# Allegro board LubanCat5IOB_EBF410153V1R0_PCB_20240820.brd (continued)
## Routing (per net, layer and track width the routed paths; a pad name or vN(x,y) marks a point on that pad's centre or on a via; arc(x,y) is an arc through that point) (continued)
SDMMC_D3: length 115.6
  TOP w0.173: J4.75 v2(82.84,64.36) ; R278.1 v1(151.54,23.76)
  ART04 w0.16: v2(82.84,64.36) 82.36,64.84 80.38,64.84 80.04,64.5 80.04,62.47 80.46,62.04 80.46,52.35 83.71,49.1 95.27,49.1 96.19,48.17 105.48,48.17 106.4,49.1 114.41,49.1 115.38,50.07 127.87,50.07 128.34,49.6 141.31,49.6 147.37,43.53 147.37,37.72 147.58,37.51 150.43,37.51 150.75,37.19 150.75,36.9 150.56,36.71 149.06,36.71 148.87,36.52 148.87,36.26 149.06,36.07 150.56,36.07 150.75,35.88 150.75,24.55 v1(151.54,23.76)
SDMMC_DET: length 118.2
  TOP w0.152: v2(83.64,63.52) 84.04,63.92 J4.81 ; R283.1 v1(151.51,16.02) R284.2
  ART04 w0.152: v2(83.64,63.52) 83.87,63.29 83.87,55.8
  ART04 w0.16: 83.87,55.8 87.26,52.42 112.83,52.42 114.12,53.71 142.49,53.71 154.66,41.54 154.66,31.38 155.78,30.27 155.78,20.97 155.46,20.65 152.49,20.65 152.1,20.26 152.1,16.6 v1(151.51,16.02)
SIM_CLK0: length 44.1
  TOP w0.152: J23.12 140.1,59.74 142,57.84 142,40.67 142.68,39.99 147.65,39.99 148.23,39.41 148.23,27.73 v1(147.57,27.07)
  BOTTOM w0.173: R259.1 v1(147.57,27.07)
SIM_DATA0: length 45.1
  TOP w0.152: v1(147.57,25.92) 148.74,27.09 148.74,40.03 147.98,40.79 143.45,40.79 142.8,41.44 142.8,58.05 140.9,59.95 J23.10
  BOTTOM w0.173: R260.1 v1(147.57,25.92)
SIM_RST0: length 43
  TOP w0.152: J23.14 139.3,59.55 141.2,57.65 141.2,40.15 142.15,39.19 147.32,39.19 147.65,38.86 147.65,28.29 v1(147.57,28.21)
  BOTTOM w0.173: R258.1 v1(147.57,28.21)
SIM_VDD: length 65.9
  TOP w0.254: J23.8 141.7,60.17 143.6,58.27 143.6,42.1 144.11,41.59 150.24,41.59 150.75,41.08 150.75,27.7 151.26,27.19 ; v1(157.15,27.19) v1(160.15,27.19) ; v1(147.57,24.78) 149.3,26.51 150.57,26.51 151.26,27.19 ; 151.26,27.19 v1(154.17,27.19)
  BOTTOM w0.254: R253.1 v1(147.57,24.78) ; v1(160.15,27.19) 160.15,23.28 159.64,22.77 J21.1 ; v1(154.17,27.19) U30.6 155.41,27.87 156.08,27.19 v1(157.15,27.19)
SPK_CTRL: length 88.1
  TOP w0.152: J4.58 79.24,67.32 v2(78.84,66.92) ; R345.1 26.04,69.1 v1(26.16,69.23) ; v1(36.2,67.97) R351.1 36.96,67.48 37.26,67.17 39.95,67.17 40.26,67.48 40.26,69.08 40.83,69.65 v1(52.41,69.65)
  ART03 w0.152: v1(36.2,67.97) 35.37,68.8 33.38,68.8 32.94,69.23 v1(26.16,69.23)
  ART04 w0.152: v1(52.41,69.65) 53.37,68.69 53.37,54.35 54.46,53.25 73.53,53.25 74.47,54.19 74.47,66.26 75.03,66.82 75.03,68.01 75.34,68.32 77.44,68.32 v2(78.84,66.92)
SPK_LN: length 5.8
  TOP w0.381: L19.2 28.19,82.32 C301.1 27.16,83.35 J42.1
SPK_LP: length 5.7
  TOP w0.381: L27.2 24.38,82.45 C300.1 25.16,83.22 J42.2
SPK_RN: length 5.8
  TOP w0.381: J43.1 38.45,83.37 C311.1 39.5,82.32 L28.2
SPK_RP: length 5.7
  TOP w0.381: J43.2 36.45,83.08 C310.1 35.69,82.32 L29.2
SYS_LED: length 200.4
  TOP w0.152: v1(80.64,41.46) 80.64,29.43 81.1,28.97 81.1,23.81 80.84,23.55 J2.65 ; v1(157.71,41.87) 157.71,34.9 158.01,34.59 169.91,34.59 170.26,34.94 170.26,83.91 169.91,84.25 167.66,84.25 167.31,84.6 167.31,94.89 166.55,95.66 151.1,95.66 150.76,96 R334.1
  ART03 w0.152: v1(114.84,43.18) 113.54,41.87 110.97,41.87 108.61,39.51 82.59,39.51 v1(80.64,41.46)
  BOTTOM w0.152: v1(114.84,43.18) 115.44,42.58 130.38,42.58 131,41.96 157.62,41.96 v1(157.71,41.87)
TYPEC0_SBU1: length 72.4
  TOP w0.132: J3.84 58.87,68.99 58.95,69.07 58.95,69.29 v2(58.67,69.57)
  ART03 w0.114: v2(58.67,69.57) 58.93,69.32 58.93,68.31 59.88,67.35 63.1,67.35 64.07,68.32 64.07,82.3 63.58,82.79 60.3,82.79 59.72,83.38 46.18,83.38 45.06,82.26 42.93,82.26 42.29,82.9 40.03,82.9 38.4,84.52 38.4,85.51 37.59,86.32 37.59,88.14 v1(37.85,88.41)
  BOTTOM w0.132: v1(37.85,88.41) 37.59,88.67 37.59,89.14 37.19,89.55 31.04,89.55 29.93,88.44 23.42,88.44 22.85,89.01 22.85,90.04 C84.2
TYPEC0_SBU1_DC: length 97.9
  TOP w0.152: J4.93 86.44,63.92 v2(86.04,63.52)
  ART04 w0.152: v2(86.04,63.52) 86.47,63.95 88.06,63.95 88.24,64.12 88.24,66.99 87.91,67.32 86.23,67.32 85.9,67.66 83.59,67.66 83.29,67.96 83.29,68.93 82.98,69.23 81.05,69.23 80.75,69.53 80.75,71.97 80.44,72.28 52.5,72.28 51.36,73.42 49.83,73.42 49.53,73.73 49.53,80.28 50.16,80.91 50.16,83.02 50.47,83.33 51.64,83.33 51.94,83.63 51.94,86.3 51.1,87.14 51.1,89.04 50.52,89.63 28.19,89.63 27.03,90.79 24.81,90.79 v1(24.25,90.24)
  BOTTOM w0.173: R92.2 v1(24.25,90.24)
TYPEC0_SBU2: length 71.6
  TOP w0.132: J3.86 59.27,69.09 59.19,69.17 59.19,69.34 v2(59.42,69.57)
  ART03 w0.114: v2(59.42,69.57) 59.17,69.32 59.17,68.41 59.98,67.59 63,67.59 63.83,68.42 63.83,82.2 63.48,82.55 60.2,82.55 59.62,83.14 46.28,83.14 45.16,82.02 42.83,82.02 42.19,82.65 39.93,82.65 38.16,84.42 38.16,85.41 37.35,86.22 37.35,88.14 v1(37.09,88.41)
  BOTTOM w0.132: C85.2 22.61,90.04 22.61,88.91 23.32,88.2 30.03,88.2 31.13,89.31 37.09,89.31 37.35,89.04 37.35,88.67 v1(37.09,88.41)
TYPEC0_SBU2_DC: length 93.3
  TOP w0.152: J4.95 v2(86.84,64.36)
  ART04 w0.152: v1(20.46,90.67) 23.04,90.67 24.58,89.13 48.26,89.13 48.64,88.75 48.64,87.14 49.91,85.87 49.91,84.09 49.15,83.33 49.15,73.22 49.45,72.91 51,72.91 51.31,72.61 51.31,71.95 51.61,71.64 56.67,71.64 57.18,71.13 64.08,71.13 64.69,71.74 77.37,71.74 78.05,71.06 79.91,71.06 80.21,70.75 80.21,69 80.52,68.7 82.14,68.7 82.45,68.39 82.45,66.56 82.68,66.33 83.01,66.33 83.39,65.95 86.48,65.95 86.84,65.6 v2(86.84,64.36)
  BOTTOM w0.152: v1(20.46,90.67) 20.46,91.69 R94.2
TYPEC0_SSRX1N: length 52.3
  TOP w0.132: R86.2 30.4,90.86 arc(30.36,90.8) 30.35,90.73 30.35,90.61 arc(30.41,90.28) 30.6,89.99 arc(30.81,89.85) 31.06,89.8 33.01,89.8 arc(33.42,89.72) 33.78,89.49 33.91,89.36 arc(34.14,89) 34.22,88.59 34.22,86.16 arc(34.25,86.05) 34.31,85.95 v1(34.5,85.77) ; J3.80 58.07,67.98 57.99,67.9 57.99,67.78 arc(58.01,67.69) 58.06,67.61 v2(58.27,67.4)
  ART03 w0.114: v1(34.5,85.77) 34.35,85.62 arc(34.25,85.47) 34.21,85.29 34.21,84.73 arc(34.24,84.58) 34.33,84.46 34.47,84.32 arc(34.59,84.23) 34.74,84.2 35.62,84.2 arc(35.9,84.15) 36.14,83.99 36.29,83.85 arc(36.44,83.61) 36.5,83.33 36.5,82.35 arc(36.64,82) 36.99,81.85 38.22,81.85 arc(38.44,81.81) 38.62,81.69 39.05,81.26 arc(39.43,81) 39.88,80.91 41.67,80.91 arc(41.89,80.87) 42.08,80.75 42.17,80.65 arc(42.3,80.56) 42.46,80.53 45.09,80.53 arc(45.5,80.61) 45.84,80.84 46.55,81.55 arc(47.03,81.87) 47.58,81.98 57.05,81.98 arc(57.43,81.9) 57.76,81.69 arc(57.98,81.36) 58.05,80.98 58.05,75.54 arc(58.12,75.19) 58.32,74.89 arc(58.58,74.5) 58.67,74.04 58.67,70.73 arc(58.6,70.38) 58.4,70.07 arc(58.22,69.8) 58.15,69.48 58.15,67.69 arc(58.18,67.53) v2(58.27,67.4)
TYPEC0_SSRX1P: length 53.2
  TOP w0.132: v2(57.52,67.4) 57.7,67.58 arc(57.74,67.64) 57.75,67.7 57.75,67.8 57.67,67.88 J3.78 ; v1(33.71,85.77) 33.9,85.95 arc(33.96,86.05) 33.99,86.16 33.99,86.42 arc(33.93,86.55) 33.79,86.61 arc(33.66,86.66) 33.6,86.8 33.6,86.95 arc(33.66,87.08) 33.79,87.14 arc(33.93,87.19) 33.99,87.33 33.99,88.59 arc(33.92,88.91) 33.74,89.19 33.61,89.32 arc(33.33,89.5) 33.01,89.57 31.06,89.57 arc(30.72,89.63) 30.43,89.82 arc(30.19,90.19) 30.11,90.61 30.11,90.73 arc(30.09,90.8) 30.05,90.86 R85.2
  ART03 w0.114: v1(33.71,85.77) 33.85,85.63 arc(33.94,85.49) 33.97,85.33 33.97,84.73 arc(34.02,84.49) 34.16,84.29 34.3,84.15 arc(34.5,84.01) 34.74,83.96 35.62,83.96 arc(35.81,83.93) 35.97,83.82 36.12,83.67 arc(36.22,83.52) 36.26,83.33 36.26,82.35 arc(36.47,81.83) 36.99,81.61 38.22,81.61 arc(38.35,81.59) 38.45,81.52 38.88,81.09 arc(39.34,80.78) 39.88,80.67 41.67,80.67 arc(41.8,80.65) 41.91,80.58 42,80.48 arc(42.21,80.34) 42.46,80.29 45.09,80.29 arc(45.59,80.39) 46.01,80.67 46.72,81.38 arc(47.12,81.65) 47.58,81.74 57.05,81.74 arc(57.34,81.68) 57.59,81.52 arc(57.75,81.27) 57.81,80.98 57.81,75.54 arc(57.9,75.1) 58.15,74.72 arc(58.36,74.41) 58.43,74.04 58.43,70.73 arc(58.38,70.47) 58.23,70.24 arc(57.99,69.89) 57.91,69.48 57.91,68.96 arc(57.86,68.84) 57.75,68.79 arc(57.63,68.74) 57.58,68.63 57.58,68.5 arc(57.63,68.38) 57.75,68.33 arc(57.86,68.29) 57.91,68.17 57.91,67.93 arc(57.89,67.8) 57.81,67.69 v2(57.52,67.4)
TYPEC0_SSRX2N: length 51.7
  TOP w0.132: J3.70 56.07,67.98 55.99,67.9 55.99,67.78 arc(56.01,67.69) 56.06,67.61 v2(56.27,67.4) ; v1(30.1,85.74) 29.86,85.98 arc(29.82,86.04) 29.8,86.12 29.8,87.22 arc(29.71,87.7) 29.44,88.1 29.36,88.18 arc(28.96,88.45) 28.48,88.54 24.29,88.54 arc(24.08,88.59) 23.9,88.7 arc(23.78,88.88) 23.74,89.09 23.74,90.73 arc(23.76,90.8) 23.8,90.86 R91.2
  ART03 w0.114: v1(30.1,85.74) 29.96,85.6 arc(29.86,85.45) 29.83,85.29 29.83,85.27 arc(29.86,85.13) 29.93,85.02 33.55,81.4 34.48,80.47 arc(34.78,80.27) 35.13,80.2 arc(35.86,80.06) 36.47,79.65 36.74,79.38 arc(37.11,79.13) 37.55,79.05 47.89,79.05 arc(48.29,78.97) 48.63,78.74 arc(48.92,78.54) 49.27,78.48 53.8,78.48 arc(54.62,78.13) 54.97,77.31 54.97,74.51 arc(55.04,74.14) 55.25,73.82 55.79,73.28 arc(56.13,72.77) 56.25,72.17 56.25,68.96 arc(56.21,68.77) 56.1,68.6 56.1,68.6 arc(56.04,68.51) 56.02,68.41 56.02,67.82 arc(56.05,67.67) 56.14,67.54 v2(56.27,67.4)
TYPEC0_SSRX2P: length 52
  TOP w0.132: J3.68 55.67,67.88 55.75,67.8 55.75,67.7 arc(55.74,67.64) 55.7,67.58 v2(55.52,67.4) ; R89.2 23.45,90.86 arc(23.49,90.8) 23.5,90.73 23.5,90.47 arc(23.46,90.36) 23.35,90.31 arc(23.24,90.27) 23.19,90.16 23.19,89.94 arc(23.24,89.83) 23.35,89.78 arc(23.46,89.74) 23.5,89.63 23.5,89.09 arc(23.56,88.79) 23.73,88.54 arc(23.99,88.37) 24.29,88.31 28.48,88.31 arc(28.87,88.23) 29.2,88.01 29.27,87.94 arc(29.49,87.61) 29.57,87.22 29.57,86.13 arc(29.54,86) 29.47,85.89 v1(29.32,85.74)
  ART03 w0.114: v1(29.32,85.74) 29.46,85.6 arc(29.56,85.45) 29.59,85.29 29.59,85.27 arc(29.63,85.04) 29.76,84.84 33.38,81.23 34.31,80.3 arc(34.68,80.05) 35.13,79.96 arc(35.76,79.84) 36.3,79.48 36.57,79.21 arc(37.02,78.91) 37.55,78.81 47.89,78.81 arc(48.2,78.74) 48.46,78.57 arc(48.83,78.32) 49.27,78.23 53.8,78.23 arc(54.45,77.96) 54.72,77.31 54.72,74.51 arc(54.82,74.05) 55.08,73.65 55.62,73.11 arc(55.91,72.68) 56.01,72.17 56.01,68.96 arc(55.99,68.86) 55.93,68.77 arc(55.82,68.6) 55.78,68.41 55.78,67.82 arc(55.75,67.67) 55.66,67.54 v2(55.52,67.4)
TYPEC0_SSTX1N: length 50.7
  TOP w0.132: J3.76 57.27,69.09 57.19,69.17 57.19,69.27 arc(57.21,69.34) 57.24,69.39 v2(57.42,69.57) ; C80.2 28.02,90.86 arc(28.06,90.8) 28.07,90.73 28.07,90.16 arc(28.13,89.89) 28.29,89.65 28.36,89.58 arc(28.71,89.34) 29.13,89.26 arc(29.7,89.15) 30.18,88.82 30.94,88.07 arc(31.31,87.51) 31.45,86.85 31.45,86.13 arc(31.42,86.02) 31.36,85.93 v1(31.17,85.74)
  ART03 w0.114: v2(57.42,69.57) 57.29,69.71 arc(57.2,69.84) 57.17,69.99 57.17,78.97 arc(57.12,79.22) 56.98,79.44 56.9,79.52 arc(56.68,79.66) 56.43,79.71 55.84,79.71 arc(55.48,79.78) 55.17,79.98 55.11,80.05 arc(54.68,80.33) 54.18,80.43 48.87,80.43 arc(48.47,80.35) 48.13,80.13 arc(47.74,79.86) 47.27,79.77 40.17,79.77 arc(39.57,79.89) 39.07,80.23 38.76,80.54 arc(38.39,80.78) 37.97,80.86 36.6,80.86 arc(36.32,80.92) 36.08,81.08 35.87,81.29 arc(35.72,81.52) 35.66,81.8 35.66,82.33 arc(35.38,83) 34.71,83.28 arc(34.36,83.35) 34.05,83.55 33.63,83.97 arc(33.37,84.37) 33.27,84.83 33.27,86.39 arc(33.21,86.69) 33.04,86.95 arc(32.72,87.17) 32.33,87.24 arc(32,87.18) 31.72,86.99 31.63,86.9 arc(31.49,86.7) 31.44,86.45 31.44,86.19 arc(31.41,86.03) 31.32,85.88 v1(31.17,85.74)
TYPEC0_SSTX1P: length 50.8
  TOP w0.132: C79.2 28.37,90.86 arc(28.33,90.8) 28.31,90.73 28.31,90.16 arc(28.35,89.98) 28.45,89.82 28.53,89.75 arc(28.8,89.56) 29.13,89.5 arc(29.79,89.37) 30.35,88.99 31.11,88.24 arc(31.53,87.6) 31.68,86.85 31.68,86.13 arc(31.71,86.02) 31.77,85.93 v1(31.96,85.74) ; v2(56.67,69.57) 56.89,69.36 arc(56.94,69.29) 56.95,69.2 56.95,69.07 56.87,68.99 J3.74
  ART03 w0.114: v2(56.67,69.57) 56.86,69.76 arc(56.91,69.83) 56.93,69.92 56.93,70.16 arc(56.89,70.24) 56.81,70.28 arc(56.73,70.31) 56.69,70.39 56.69,70.62 arc(56.73,70.7) 56.81,70.74 arc(56.89,70.77) 56.93,70.85 56.93,71.08 arc(56.89,71.16) 56.81,71.19 arc(56.73,71.23) 56.69,71.31 56.69,71.53 arc(56.73,71.62) 56.81,71.65 arc(56.89,71.68) 56.93,71.77 56.93,71.99 arc(56.89,72.07) 56.81,72.11 arc(56.73,72.14) 56.69,72.22 56.69,72.45 arc(56.73,72.53) 56.81,72.56 arc(56.89,72.6) 56.93,72.68 56.93,78.97 arc(56.9,79.13) 56.81,79.27 56.73,79.35 arc(56.59,79.43) 56.43,79.47 55.84,79.47 arc(55.38,79.56) 55,79.81 54.94,79.88 arc(54.59,80.11) 54.18,80.19 48.87,80.19 arc(48.56,80.13) 48.31,79.96 48.3,79.96 arc(47.83,79.64) 47.27,79.53 40.17,79.53 arc(39.48,79.67) 38.9,80.06 38.59,80.36 arc(38.3,80.56) 37.97,80.62 36.6,80.62 arc(36.23,80.7) 35.91,80.9 35.7,81.12 arc(35.49,81.43) 35.42,81.8 35.42,82.33 arc(35.21,82.83) 34.71,83.03 arc(34.26,83.12) 33.88,83.38 33.46,83.8 arc(33.14,84.27) 33.03,84.83 33.03,86.39 arc(32.99,86.6) 32.87,86.77 32.87,86.78 arc(32.62,86.94) 32.33,87 arc(32.09,86.95) 31.89,86.82 31.8,86.73 arc(31.72,86.6) 31.69,86.45 31.69,86.19 arc(31.72,86.03) 31.81,85.88 v1(31.96,85.74)
TYPEC0_SSTX2N: length 52.6
  TOP w0.132: C83.2 21.42,90.86 arc(21.46,90.8) 21.47,90.73 21.47,90.33 arc(21.51,90.13) 21.62,89.97 22.24,89.35 arc(22.45,89.04) 22.52,88.68 22.52,87.84 arc(22.5,87.73) 22.43,87.63 v1(22.25,87.44) ; v2(55.42,69.57) 55.24,69.39 arc(55.21,69.34) 55.19,69.27 55.19,69.17 55.27,69.09 J3.66
  ART03 w0.114: v1(22.25,87.44) 22.39,87.59 arc(22.49,87.73) 22.52,87.9 22.52,88.13 arc(22.7,88.56) 23.13,88.74 23.78,88.74 arc(24.15,88.58) 24.31,88.21 24.31,86.05 arc(24.66,85.19) 25.52,84.84 28.01,84.84 arc(28.65,84.71) 29.19,84.35 32.78,80.76 arc(33.13,80.24) 33.25,79.63 arc(33.29,79.4) 33.42,79.21 arc(33.62,79.08) 33.84,79.03 34.83,79.03 arc(35.2,78.96) 35.51,78.75 35.6,78.67 arc(36.34,78.17) 37.23,77.99 47.64,77.99 arc(47.86,77.95) 48.05,77.83 48.27,77.6 arc(48.4,77.52) 48.55,77.48 53.32,77.48 arc(53.85,77.26) 54.08,76.73 54.08,74.33 arc(54.18,73.82) 54.47,73.38 54.74,73.11 arc(55.06,72.64) 55.17,72.08 55.17,69.99 arc(55.2,69.84) 55.29,69.71 v2(55.42,69.57)
TYPEC0_SSTX2P: length 53.3
  TOP w0.132: J3.64 54.87,68.99 54.95,69.07 54.95,69.2 arc(54.94,69.29) 54.89,69.36 v2(54.67,69.57) ; v1(23.03,87.44) 22.84,87.63 arc(22.78,87.73) 22.76,87.84 22.76,88.68 arc(22.67,89.13) 22.41,89.51 21.79,90.14 arc(21.73,90.23) 21.71,90.33 21.71,90.73 arc(21.72,90.8) 21.76,90.86 C82.2
  ART03 w0.114: v2(54.67,69.57) 54.81,69.71 arc(54.9,69.84) 54.93,69.99 54.93,70.23 arc(54.89,70.33) 54.79,70.37 arc(54.7,70.41) 54.66,70.5 54.66,70.69 arc(54.7,70.78) 54.79,70.82 arc(54.89,70.86) 54.93,70.96 54.93,71.2 arc(54.88,71.3) 54.78,71.34 arc(54.68,71.39) 54.64,71.49 54.64,71.66 arc(54.68,71.76) 54.78,71.8 arc(54.88,71.84) 54.93,71.95 54.93,72.08 arc(54.83,72.55) 54.57,72.94 54.3,73.21 arc(53.96,73.73) 53.84,74.33 53.84,76.73 arc(53.68,77.09) 53.32,77.24 48.55,77.24 arc(48.31,77.29) 48.1,77.43 47.88,77.65 arc(47.77,77.73) 47.64,77.75 37.23,77.75 arc(36.25,77.95) 35.42,78.5 35.34,78.58 arc(35.11,78.74) 34.83,78.79 33.84,78.79 arc(33.52,78.86) 33.25,79.04 arc(33.07,79.31) 33.01,79.63 arc(32.9,80.15) 32.61,80.59 29.02,84.18 arc(28.56,84.49) 28.01,84.6 25.52,84.6 arc(24.49,85.02) 24.07,86.05 24.07,86.3 arc(24.02,86.4) 23.92,86.45 23.87,86.45 arc(23.77,86.49) 23.72,86.59 23.72,86.76 arc(23.77,86.86) 23.87,86.9 23.92,86.9 arc(24.02,86.95) 24.07,87.05 24.07,87.22 arc(24.02,87.32) 23.92,87.36 arc(23.82,87.4) 23.77,87.51 23.77,87.67 arc(23.82,87.78) 23.92,87.82 arc(24.02,87.86) 24.07,87.97 24.07,88.21 arc(23.98,88.41) 23.78,88.5 23.13,88.5 arc(22.87,88.39) 22.76,88.13 22.76,87.9 arc(22.79,87.73) 22.89,87.59 v1(23.03,87.44)
TYPEC0_USB20_OTG_DM: length 63.7
  TOP w0.132: J3.98 61.67,69.09 61.59,69.17 61.59,69.41 arc(61.63,69.58) 61.72,69.73 v2(61.87,69.88) ; v1(25.52,89.57) 25.7,89.76 arc(25.77,89.86) 25.79,89.97 25.79,91.06 arc(25.75,91.15) 25.66,91.19 R82.2
  ART03 w0.114: v2(61.87,69.88) 61.71,69.72 arc(61.61,69.56) 61.57,69.37 61.57,68.89 arc(61.68,68.61) 61.96,68.49 62.51,68.49 arc(62.8,68.61) 62.92,68.9 62.92,70.34 arc(62.89,70.46) 62.82,70.57 62.59,70.8 arc(62.46,70.99) 62.42,71.21 62.42,74.94 arc(62.46,75.15) 62.59,75.34 62.88,75.63 arc(62.95,75.74) 62.98,75.87 62.98,80.78 arc(62.81,81.19) 62.4,81.36 59.39,81.36 arc(58.96,81.44) 58.61,81.68 58.19,82.1 arc(57.83,82.34) 57.4,82.43 47.3,82.43 arc(46.67,82.3) 46.14,81.95 45.76,81.56 arc(45.28,81.24) 44.72,81.13 42.71,81.13 arc(42.4,81.19) 42.13,81.37 arc(41.8,81.59) 41.43,81.66 40.31,81.66 arc(39.56,81.81) 38.93,82.24 35.6,85.56 arc(35.34,85.96) 35.24,86.43 35.24,86.98 arc(35.18,87.29) 35,87.56 arc(34.62,87.81) 34.18,87.9 30.23,87.9 arc(30.11,87.85) 30.06,87.73 30.06,87.68 arc(30.01,87.57) 29.9,87.52 29.77,87.52 arc(29.65,87.57) 29.6,87.68 29.6,87.73 arc(29.55,87.85) 29.44,87.9 29.31,87.9 arc(29.19,87.85) 29.15,87.73 arc(29.1,87.62) 28.98,87.57 28.85,87.57 arc(28.74,87.62) 28.69,87.73 arc(28.64,87.85) 28.52,87.9 28.4,87.9 arc(28.28,87.85) 28.23,87.73 arc(28.18,87.62) 28.07,87.57 27.94,87.57 arc(27.82,87.62) 27.77,87.73 arc(27.73,87.85) 27.61,87.9 27.48,87.9 arc(27.37,87.85) 27.32,87.73 arc(27.27,87.62) 27.15,87.57 27.02,87.57 arc(26.91,87.62) 26.86,87.73 arc(26.81,87.85) 26.69,87.9 26.45,87.9 arc(26.18,87.95) 25.95,88.11 arc(25.83,88.29) 25.79,88.49 25.79,89.12 arc(25.75,89.29) 25.66,89.43 v1(25.52,89.57)
TYPEC0_USB20_OTG_DP: length 62.8
  TOP w0.132: R81.2 26.16,91.19 arc(26.07,91.15) 26.03,91.06 26.03,89.97 arc(26.05,89.86) 26.11,89.76 v1(26.3,89.57) ; J3.96 61.27,68.99 61.35,69.07 61.35,69.5 arc(61.33,69.64) 61.25,69.75 v2(61.12,69.88)
  ART03 w0.114: v2(61.12,69.88) 61.23,69.77 arc(61.3,69.67) 61.33,69.54 61.33,68.89 arc(61.51,68.44) 61.96,68.25 62.51,68.25 arc(62.97,68.44) 63.16,68.9 63.16,70.34 arc(63.11,70.56) 62.99,70.74 62.76,70.97 arc(62.69,71.08) 62.66,71.21 62.66,74.94 arc(62.69,75.06) 62.76,75.17 63.05,75.46 arc(63.18,75.65) 63.22,75.87 63.22,80.78 arc(62.98,81.36) 62.4,81.6 59.39,81.6 arc(59.06,81.67) 58.78,81.85 58.36,82.27 arc(57.92,82.56) 57.4,82.67 47.3,82.67 arc(46.58,82.52) 45.97,82.12 45.59,81.73 arc(45.19,81.46) 44.72,81.37 42.71,81.37 arc(42.49,81.42) 42.3,81.54 arc(41.9,81.81) 41.43,81.9 40.31,81.9 arc(39.65,82.03) 39.1,82.41 35.77,85.73 arc(35.56,86.05) 35.48,86.43 35.48,86.98 arc(35.4,87.38) 35.17,87.73 arc(34.72,88.03) 34.18,88.14 26.45,88.14 arc(26.27,88.18) 26.12,88.28 arc(26.05,88.38) 26.03,88.49 26.03,89.12 arc(26.06,89.29) 26.16,89.43 v1(26.3,89.57)
TYPEC0_USB20_OTG_ID: length 4.8
  TOP w0.152: J3.90 60.07,70.04 61.01,70.98 61.01,72.07 R78.2
TYPEC0_USB20_VBUSDET: length 3.6
  TOP w0.152: J3.92 60.47,69.83 61.6,70.97 R77.2
TYPEC1_SSRX1N: length 62.5
  TOP w0.132: J4.38 75.24,67.88 75.16,67.8 75.16,67.35 v2(75.43,67.08)
  ART03 w0.114: v2(75.43,67.08) 75.16,66.8 75.16,66.28 74.8,65.93 73.79,65.93 73.42,66.3 73.42,71.91 73.81,72.3 80.19,72.3 81.28,73.4 103.75,73.4 104.24,73.89 106.92,73.89 110.2,77.17 112.71,77.17 116.79,81.24 116.79,81.86 117.38,82.45 118.92,82.45 119.22,82.15 119.22,81.75 v1(119.63,81.34)
  BOTTOM w0.132: v1(119.63,81.34) R83.2
TYPEC1_SSRX1P: length 62.4
  TOP w0.132: J4.36 74.84,67.88 74.92,67.8 74.92,67.35 v2(74.65,67.08)
  ART03 w0.114: v2(74.65,67.08) 74.91,66.81 74.91,66.38 74.7,66.17 73.89,66.17 73.66,66.4 73.66,67.91 arc(73.7,68.02) 73.81,68.06 arc(73.91,68.1) 73.96,68.21 73.96,68.37 arc(73.91,68.47) 73.81,68.52 arc(73.7,68.56) 73.66,68.67 73.66,68.83 arc(73.7,68.93) 73.81,68.97 arc(73.91,69.02) 73.96,69.12 73.96,69.28 arc(73.91,69.39) 73.81,69.43 arc(73.7,69.48) 73.66,69.58 73.66,69.74 arc(73.7,69.85) 73.81,69.89 arc(73.91,69.93) 73.96,70.04 73.96,70.2 arc(73.91,70.3) 73.81,70.35 arc(73.7,70.39) 73.66,70.5 73.66,71.81 73.91,72.06 80.29,72.06 81.38,73.15 103.85,73.15 104.34,73.65 107.02,73.65 110.3,76.93 112.81,76.93 115.12,79.23 115.49,79.23 115.81,79.55 115.81,79.92 116.13,80.25 116.5,80.25 116.83,80.57 116.83,80.94 117.03,81.14 117.03,81.76 117.47,82.21 118.82,82.21 118.98,82.05 118.98,81.5 118.82,81.34 v1(118.62,81.34)
  BOTTOM w0.132: v1(118.62,81.34) R84.2
TYPEC1_SSTX1N: length 62.8
  TOP w0.132: J4.34 74.44,69.09 74.36,69.17 74.36,69.68 74.62,69.95 75.09,69.95 v1(75.33,69.71)
  ART03 w0.114: v1(75.33,69.71) 75.6,69.98 76.09,69.98 76.86,70.75 77.17,70.75 arc(77.26,70.72) 77.29,70.64 arc(77.32,70.56) 77.4,70.53 77.63,70.53 arc(77.71,70.56) 77.75,70.64 arc(77.78,70.72) 77.86,70.75 78.09,70.75 arc(78.17,70.72) 78.2,70.64 arc(78.24,70.56) 78.32,70.53 78.55,70.53 arc(78.63,70.56) 78.66,70.64 arc(78.69,70.72) 78.78,70.75 79,70.75 arc(79.08,70.72) 79.12,70.64 arc(79.15,70.56) 79.23,70.53 79.46,70.53 arc(79.54,70.56) 79.58,70.64 arc(79.61,70.72) 79.69,70.75 80.22,70.75 81.74,72.27 104.23,72.27 104.65,72.68 107.86,72.68 111.29,76.11 114.05,76.11 116.99,79.06 122.89,79.06 123.39,79.57 123.39,81.94 123.8,82.35 126.33,82.35 126.63,82.05 126.63,81.73 v1(126.24,81.34)
  BOTTOM w0.132: v1(126.24,81.34) C75.2
TYPEC1_SSTX1P: length 62.9
  TOP w0.132: J4.32 74.04,69.09 74.12,69.17 74.12,69.78 74.52,70.19 75.02,70.19 v1(75.33,70.49)
  ART03 w0.114: v1(75.33,70.49) 75.6,70.22 75.99,70.22 76.76,71 80.12,71 81.64,72.51 104.13,72.51 104.55,72.93 107.76,72.93 111.19,76.35 113.95,76.35 116.89,79.3 122.79,79.3 123.15,79.67 123.15,82.04 123.7,82.59 126.43,82.59 126.87,82.15 126.87,81.73 v1(127.25,81.34)
  BOTTOM w0.132: v1(127.25,81.34) C76.2
TYPEC1_USB20_OTG_DM: length 67.3
  TOP w0.132: v2(70.21,67.07) 69.96,67.32 69.96,67.8 70.04,67.88 J4.12
  ART03 w0.114: v2(70.21,67.07) 69.99,66.84 69.99,66.26 70.21,66.03 72.07,66.03 72.48,66.43 72.48,72.9 73.38,73.8 80.16,73.8 81.2,74.84 106.29,74.84 109.48,78.03 111.7,78.03 117.04,83.37 120.51,83.37 121.28,82.61 121.28,81.73 v1(121.67,81.34)
  BOTTOM w0.132: v1(121.67,81.34) R79.2
TYPEC1_USB20_OTG_DP: length 67.4
  TOP w0.132: J4.10 69.64,67.88 69.72,67.8 69.72,67.32 v2(69.47,67.07)
  ART03 w0.114: v1(120.65,81.34) 120.9,81.34 121.04,81.48 121.04,82.51 120.41,83.13 117.14,83.13 111.8,77.79 109.58,77.79 106.39,74.6 81.3,74.6 80.26,73.56 73.48,73.56 72.72,72.8 72.72,66.33 72.17,65.79 70.11,65.79 69.74,66.16 69.74,66.79 v2(69.47,67.07)
  BOTTOM w0.132: v1(120.65,81.34) R80.2
TYPEC1_USB20_VBUSDET: length 95.2
  TOP w0.152: v2(71.64,66.92) 71.24,67.32 J4.18
  ART03 w0.152: v2(71.64,66.92) 71.12,67.44 71.12,70.37 71.55,70.8 71.55,73.37 72.59,74.41 72.59,75.43 73.21,76.05 95.85,76.05 96.34,76.55 106.4,76.55 107.67,77.81 107.67,77.82 109.22,79.36 111.15,79.36 115.8,84.01 129.82,84.01 130.51,84.7 132.33,84.7 v1(133.34,85.71)
  BOTTOM w0.152: v1(133.34,85.71) 132.72,86.33 132.72,100.4 132.41,100.7 C253.1 R149.1 R150.2
TYPEC_CC1: length 32.1
  TOP w0.152: v1(20.69,88.14) U5.11 21,87.58 21.15,87.43 U5.10
  TOP w0.173: J8.A5 v1(26.65,95.14)
  BOTTOM w0.152: v1(26.65,95.14) 27.33,95.14 27.57,95.38 D10.2 27.56,95.89 27.56,98.44 27.3,98.69 24.69,98.69 24.38,99 24.38,99.84 24,100.22 22.74,100.22 21.98,99.46 19.94,99.46 19.43,98.94 19.43,94.38 18.63,93.58 18.63,92 18.85,91.78 18.85,90.87 17.99,90.02 17.99,88.01 18.34,87.67 19.91,87.67 C78.1 20.69,87.39 v1(20.69,88.14)
TYPEC_CC2: length 22.2
  TOP w0.152: v1(19.19,88.14) U5.14 18.88,87.58 18.73,87.43 U5.1
  TOP w0.173: J8.B5 v1(25.41,98.19)
  BOTTOM w0.152: D11.2 25.26,98.05 v1(25.41,98.19) 25.29,98.31 24.21,98.31 23.88,98.64 23.88,99.68 23.72,99.84 22.86,99.84 22.12,99.1 20.09,99.1 19.79,98.8 19.79,94.23 18.99,93.43 18.99,92.28 19.24,92.02 19.24,92.02 19.85,91.41 19.85,89.46 C77.1 19.19,88.79 v1(19.19,88.14)
TYPEC_DM: length 19.6
  TOP w0.132: R82.1 25.6,92.19 25.8,92.39 25.8,93.57 v1(25.15,94.22) 25.65,94.22 25.78,94.36 25.78,95.02 25.65,95.15 J8.A7 ; v1(26.55,99.23) 26.28,98.96 26.28,98.19 26.41,98.06 J8.B7
  ART03 w0.114: v1(26.55,99.23) 26.49,99.29 26.49,100.75 26.9,101.16 27.61,101.16 28.02,100.75 28.02,97.8 27.79,97.58 26.09,97.58 25.79,97.28 25.79,94.45 25.56,94.22 v1(25.15,94.22)
TYPEC_DP: length 20.6
  TOP w0.132: R81.1 26.3,92.19 26.04,92.45 26.04,93.59 v1(26.67,94.22) 26.15,94.22 26.02,94.36 26.02,95.02 26.15,95.15 J8.A6 ; v1(25.77,99.23) 26.04,98.96 26.04,98.19 25.91,98.06 J8.B6
  ART03 w0.114: v1(25.77,99.23) 26.25,99.71 26.25,100.85 26.8,101.4 27.71,101.4 28.26,100.85 28.26,97.71 27.89,97.34 26.19,97.34 26.03,97.18 26.03,94.45 26.26,94.22 v1(26.67,94.22)
TYPEC_SSRXN1: length 13.8
  TOP w0.132: R86.1 30.21,92.72 U8.5 U8.6 30.21,94.48 arc(30.2,94.55) 30.15,94.61 30.08,94.69 30.08,94.8 30.16,94.88 arc(30.22,94.92) 30.29,94.93 30.79,94.93 arc(31.34,95.16) 31.57,95.72 31.57,98.85 arc(31.52,99.1) 31.38,99.32 arc(31.06,99.53) 30.68,99.61 28.91,99.61 arc(28.29,99.35) 28.03,98.73 28.03,98.27 arc(28.02,98.19) 27.97,98.13 27.96,98.11 arc(27.91,98.05) 27.9,97.98 J8.B10
TYPEC_SSRXN2: length 4.4
  TOP w0.132: J8.A10 24.16,95.47 23.48,94.79 23.48,94.48 23.61,94.35 U9.6 U9.5 23.61,92.72 R91.1
TYPEC_SSRXP1: length 12.8
  TOP w0.132: J8.B11 28.4,97.98 arc(28.39,98.05) 28.34,98.11 28.33,98.13 arc(28.28,98.19) 28.27,98.27 28.27,98.73 arc(28.46,99.18) 28.91,99.37 30.68,99.37 arc(30.97,99.31) 31.21,99.15 31.21,99.15 arc(31.3,99.01) 31.33,98.85 31.33,95.72 arc(31.17,95.33) 30.79,95.17 30.29,95.17 arc(30.13,95.14) 29.99,95.05 29.84,94.9 29.84,94.77 arc(29.83,94.69) 29.78,94.63 29.77,94.61 arc(29.72,94.55) 29.71,94.48 U8.7 U8.4 29.71,92.2 R85.1
TYPEC_SSRXP2: length 4.2
  TOP w0.132: J8.A11 23.66,95.31 23.24,94.89 23.24,94.48 23.11,94.35 U9.7 U9.4 23.11,92.97 23.21,92.86 23.21,92.29 R89.1
TYPEC_SSTXN1: length 4.3
  TOP w0.132: C80.1 28.21,92.72 U8.1 U8.10 28.21,94.69 27.79,95.11 27.79,95.5 27.66,95.63 J8.A3
TYPEC_SSTXN2: length 14.5
  TOP w0.132: J8.B3 24.4,97.98 arc(24.39,98.05) 24.34,98.11 24.33,98.13 arc(24.28,98.19) 24.27,98.27 24.27,98.9 arc(23.99,99.58) 23.31,99.86 21.35,99.86 arc(20.64,99.56) 20.35,98.85 20.35,95.58 arc(20.4,95.33) 20.54,95.11 arc(20.77,94.96) 21.03,94.91 21.38,94.91 arc(21.51,94.88) 21.61,94.81 21.69,94.74 arc(21.72,94.68) 21.74,94.62 21.74,94.51 arc(21.72,94.44) 21.68,94.37 21.66,94.35 arc(21.62,94.29) 21.61,94.23 U9.10 U9.1 21.69,93.24 21.69,92.8 C83.1
TYPEC_SSTXP1: length 4.2
  TOP w0.132: C79.1 28.71,92.2 U8.2 U8.9 28.71,94.53 28.03,95.21 28.03,95.52 28.16,95.65 J8.A2
TYPEC_SSTXP2: length 13.9
  TOP w0.132: J8.B2 23.9,97.98 arc(23.91,98.05) 23.96,98.11 23.97,98.13 arc(24.02,98.19) 24.03,98.27 24.03,98.9 arc(23.82,99.41) 23.31,99.62 22.75,99.62 arc(22.66,99.58) 22.63,99.5 arc(22.59,99.41) 22.51,99.38 22.22,99.38 arc(22.13,99.41) 22.1,99.5 arc(22.06,99.58) 21.98,99.62 21.35,99.62 arc(20.81,99.39) 20.58,98.85 20.58,95.58 arc(20.62,95.42) 20.71,95.28 arc(20.86,95.18) 21.03,95.15 21.38,95.15 arc(21.6,95.1) 21.78,94.98 21.86,94.91 arc(21.94,94.77) 21.98,94.62 21.98,94.51 arc(21.99,94.44) 22.03,94.38 22.05,94.35 arc(22.09,94.3) 22.11,94.23 U9.9 U9.2 22.11,93.05 21.96,92.9 21.96,92.33 C82.1
TYPEC_SUB1: length 10.7
  TOP w0.132: J8.A8 v1(25.15,95.14)
  BOTTOM w0.132: v1(25.15,95.14) 25.83,95.14 26.1,95.41 26.1,95.71 25.83,95.98 25.26,95.98 arc(25.17,95.94) 25.14,95.85 arc(25.1,95.77) 25.01,95.73 24.73,95.73 arc(24.64,95.77) 24.61,95.85 arc(24.57,95.94) 24.49,95.98 24.2,95.98 arc(24.12,95.94) 24.08,95.85 arc(24.04,95.77) 23.96,95.73 23.67,95.73 arc(23.59,95.77) 23.55,95.85 arc(23.52,95.94) 23.43,95.98 23.12,95.98 22.9,95.75 22.9,94.84 D12.2 R97.1 R92.1 23.24,92.45 C84.1
TYPEC_SUB2: length 11.5
  TOP w0.132: J8.B8 v1(26.9,98.19)
  BOTTOM w0.132: v1(26.9,98.19) 26.9,96.6 26.52,96.21 23.02,96.21 22.66,95.85 22.66,94.93 D13.2 R98.1 R94.1 22.23,92.45 C85.1
TYPEC_VBUS_EN: length 151.9
  TOP w0.152: v1(47.29,30.55) 52.35,30.55 52.65,30.85 52.65,37.56 53.31,38.22 64.77,38.22 65.07,38.52 65.07,48.63 65.38,48.94 74.04,48.94 74.35,49.24 74.35,51.85 v1(74.82,52.32) ; J4.60 v2(79.64,67.76)
  BOTTOM w0.152: R93.1 15.86,81.57 22.53,81.57 23.81,82.85 35.53,82.85 36.45,81.93 36.45,69.31 36.78,68.98 36.78,66.87 37.13,66.51 37.97,66.51 38.15,66.33 38.15,52.82 38.35,52.62 42.06,52.62 42.49,52.19 42.49,30.88 42.85,30.52 47.27,30.52 v1(47.29,30.55) ; v1(74.82,52.32) 74.82,53.9 75.34,54.42 75.34,65.19 75.79,65.65 76.58,65.65 77.14,66.21 78.31,66.21 78.44,66.33 78.44,67.88 78.74,68.19 79.21,68.19 v2(79.64,67.76)
UART2_RX: length 1.9
  TOP w0.152: R291.2 5.46,15.64 U34.2
UART2_RX_M0_DEBUG: length 87.4
  TOP w0.152: J2.78 83.24,17.34 82.93,17.03 82.93,12.26 82.63,11.95 73.15,11.95 70.74,9.54 65.66,9.54 65.28,9.92 65.28,11.95 64.85,12.38 57.05,12.38 56.86,12.2 v1(49.06,12.2) ; U34.4 v1(9.52,14.99)
  BOTTOM w0.152: v1(9.52,14.99) 9.52,13.32 10.16,12.67 35.32,12.67 35.71,12.28 46.02,12.28 46.69,11.62 48.48,11.62 v1(49.06,12.2)
UART2_TX: length 1.7
  TOP w0.152: U33.4 5.1,20.34 R290.2
UART2_TX_M0_DEBUG: length 92.3
  TOP w0.152: J2.80 83.64,17.11 83.33,16.8 83.33,12.09 82.79,11.55 73.39,11.55 70.97,9.14 65.3,9.14 64.88,9.56 64.88,11.72 64.57,12.03 57.56,12.03 57.1,11.57 47.68,11.57 v1(47.06,12.2) ; U33.2 v1(9.52,19.69)
  BOTTOM w0.152: v1(47.06,12.2) 46.51,12.74 36.17,12.74 35.73,13.18 10.52,13.18 10.01,13.69 10.01,15.24 9.52,15.73 v1(9.52,19.69)
UART4_RX: length 26.3
  TOP w0.152: R297.2 D64.1 103.51,28.72 108.66,28.72 108.97,29.02 108.97,32.48 109.27,32.78 J30.3
  BOTTOM w0.152: J28.3 110.54,23.49 110.24,23.8 110.24,31.64 J30.3
UART4_RX_M2: length 22.7
  TOP w0.152: J2.97 87.24,25.28 88.01,26.05 100.28,26.05 100.58,26.35 100.58,30.18 100.89,30.49 R297.1
UART4_TX: length 36.7
  TOP w0.152: J30.4 112.65,31.51 109.91,31.51 109.6,31.21 109.6,28.26 109.3,27.95 103.51,27.95 D63.1 R298.2
  BOTTOM w0.152: J30.4 112.9,32.78 111.76,33.92 109.91,33.92 109.6,33.62 109.6,21.8 109.91,21.49 J28.2
UART4_TX_M2: length 18.2
  TOP w0.152: J2.99 87.64,24.82 88.37,25.54 101.42,25.54 101.73,25.85 R298.1
UART7_RX: length 18.1
  TOP w0.152: R299.2 D62.1 103.62,35.08 103.89,34.81 103.89,34.05 J31.3
  BOTTOM w0.152: J29.3 104.47,21.53 104.01,21.99 104.01,31.64 J31.3
UART7_RX_M2: length 29.1
  TOP w0.152: J2.93 86.44,26.38 87.12,27.07 98.63,27.07 98.93,27.37 98.93,35.77 99.24,36.07 R299.1
UART7_TX: length 19.4
  TOP w0.152: R300.2 D61.1 103.51,31.51 106.43,31.51 J31.4
  BOTTOM w0.152: J29.2 108.53,23.53 108.84,23.84 108.84,31.64 J31.4
UART7_TX_M2: length 26
  TOP w0.152: R300.1 100.13,33.28 99.82,32.98 99.82,26.84 99.52,26.53 87.48,26.53 86.84,25.9 J2.95
USB20_DM1: length 10.2
  BOTTOM w0.132: R88.1 125.23,83.06 U11.9 U11.2 125.23,85.41 125.1,85.54 125.1,87.07 123.98,88.19 123.98,89 123.01,89.97 123.01,90.75 123.16,90.91 123.72,90.91 123.87,90.75 J9.11
USB20_DP1: length 10.5
  BOTTOM w0.132: J9.12 121.87,90.73 122.07,90.93 122.63,90.93 122.77,90.79 122.77,89.87 123.74,88.9 123.74,88.09 124.86,86.97 124.86,85.54 124.73,85.41 U11.1 U11.10 124.73,83.57 R90.1
USB20_HOST0_DM: length 51.4
  TOP w0.132: v2(85.46,67.23) 85.16,67.53 85.16,67.8 85.24,67.88 J4.88
  ART03 w0.114: v1(125.22,81.34) 124.83,80.96 124.83,79.97 arc(124.87,79.89) 124.95,79.85 arc(125.04,79.82) 125.07,79.73 125.07,79.51 arc(125.04,79.43) 124.95,79.39 arc(124.87,79.36) 124.83,79.28 124.83,78.67 124.3,78.14 117.24,78.14 113.92,74.82 111.58,74.82 110.03,73.27 110.03,71.21 109.39,70.56 90.82,70.56 88.65,68.39 85.47,68.39 85.19,68.11 85.19,67.5 v2(85.46,67.23)
  BOTTOM w0.132: v1(125.22,81.34) R88.2
USB20_HOST0_DP: length 51.2
  TOP w0.132: v2(84.67,67.23) 84.92,67.48 84.92,67.8 84.84,67.88 J4.86
  ART03 w0.114: v2(84.67,67.23) 84.95,67.5 84.95,68.21 85.37,68.63 88.55,68.63 90.72,70.8 109.29,70.8 109.79,71.31 109.79,73.37 111.48,75.06 113.82,75.06 117.14,78.38 124.2,78.38 124.59,78.77 124.59,80.96 v1(124.21,81.34)
  BOTTOM w0.132: v1(124.21,81.34) R90.2
USB20_HOST1_DM: length 66.2
  TOP w0.132: J4.82 84.04,67.88 83.96,67.8 83.96,66.79 v2(84.23,66.52) ; R107.2 v1(134.98,82.8)
  ART03 w0.114: v1(134.98,82.8) 134.59,82.42 134.35,82.42 134.19,82.57 133.89,82.57 133.73,82.42 133.43,82.42 133.27,82.57 132.98,82.57 132.82,82.42 132.52,82.42 132.36,82.57 132.06,82.57 131.9,82.42 129.19,82.42 128.71,81.94 128.71,77.79 128.44,77.51 117.44,77.51 114.17,74.25 111.75,74.25 110.63,73.13 110.63,70.28 110.31,69.97 92.17,69.97 87.87,65.67 84.2,65.67 83.96,65.91 83.96,66.24 v2(84.23,66.52)
USB20_HOST1_DP: length 66.2
  TOP w0.132: R106.2 v1(134.98,81.79) ; v2(83.45,66.52) 83.72,66.79 83.72,67.8 83.64,67.88 J4.80
  ART03 w0.114: v2(83.45,66.52) 83.72,66.24 83.72,65.81 84.1,65.43 87.97,65.43 92.27,69.73 110.41,69.73 110.87,70.18 110.87,73.03 111.85,74.01 114.27,74.01 117.54,77.27 128.54,77.27 128.96,77.69 128.96,81.84 129.29,82.17 134.59,82.17 v1(134.98,81.79)
USB20_HOST_PWR_EN: length 166.3
  TOP w0.152: v1(75.82,51.32) 75.31,50.81 75.31,46.57 74.73,45.99 66.34,45.99 66.04,45.68 66.04,37.64 65.74,37.33 53.98,37.33 53.67,37.03 J1.57 ; v1(134.76,74.93) 135.51,74.18 135.51,58.55 134.75,57.78 129.23,57.78 v1(128.65,57.21)
  ART03 w0.152: v1(75.82,51.32) 77.83,51.32 78.79,52.29 81.25,52.29 81.54,52 83.41,52 83.85,52.44 127.51,52.44 127.97,52.9 127.97,56.52 v1(128.65,57.21)
  BOTTOM w0.152: v1(134.76,74.93) 134.36,75.33 134.36,78.61 134.75,78.99 135.67,78.99 136.02,79.34 136.02,84.95 135.71,85.26 132.33,85.26 131.95,85.64 131.95,97.7 131.61,98.04 128.02,98.04 127.64,98.42 R324.1
USB20_HUB_PWR_EN: length 96.3
  TOP w0.152: v1(136.66,97.93) 131.9,97.93 131.41,98.42 119.48,98.42 118.21,99.69 100.56,99.69 100.2,100.05 86.9,100.05 86.46,99.61 86.46,97.66 v1(86.93,97.19) ; J4.64 v2(80.44,67.76)
  ART03 w0.152: v1(86.93,97.19) 86.26,96.51 86.26,95.49 85.9,95.14 85.12,95.14 84.07,94.1 84.07,87.95 83.41,87.29 78.89,87.29 78.59,86.98 78.59,84.01 v1(79.47,83.13)
  BOTTOM w0.152: v2(80.44,67.76) 80.44,76.3 80.01,76.73 80.01,77.87 79.63,78.25 79.63,82.97 v1(79.47,83.13) ; v1(136.66,97.93) 136.22,98.37 136.22,101.03 136.66,101.47 R102.1
USB30_DM: length 14.4
  BOTTOM w0.132: R79.1 121.14,83.57 U10.6 U10.5 121.14,85.41 121.01,85.54 121.01,87.1 120.03,88.08 120.03,89.08 120.98,90.03 120.98,90.55 121.97,91.54 121.97,92.07 122.99,93.09 122.99,93.89 123.25,94.16 123.61,94.16 123.87,93.89 J9.2
USB30_DP: length 14.2
  BOTTOM w0.132: J9.3 121.87,93.9 122.13,94.17 122.48,94.17 122.75,93.9 122.75,93.19 121.73,92.17 121.73,91.64 120.74,90.65 120.74,90.13 119.79,89.18 119.79,87.98 120.77,87 120.77,85.54 120.64,85.41 U10.4 U10.7 120.64,83.06 R80.1
USB30_OTG_PWR_EN: length 71.7
  TOP w0.152: v1(86.93,96.19) 87.43,96.68 87.43,98.44 87.73,98.74 96.86,98.74 97.1,98.5 116.66,98.5 v1(116.97,98.8) ; J4.62 80.04,67.32 v2(79.64,66.92)
  ART03 w0.152: v1(79.47,84.13) 79.04,84.56 79.04,86.55 79.34,86.86 83.85,86.86 84.53,87.54 84.53,93.44 84.96,93.86 85.47,93.86 86.93,95.33 v1(86.93,96.19)
  BOTTOM w0.152: v1(79.47,84.13) 79.04,83.7 79.04,82.01 78.69,81.67 78.69,78.2 79.08,77.81 79.08,76.64 80.01,75.71 80.01,67.29 v2(79.64,66.92)
  BOTTOM w0.173: R96.1 v1(116.97,98.8)
USB30_RXN: length 26.2
  BOTTOM w0.132: R83.1 119.63,84.17 U10.9 U10.2 119.64,85.41 119.51,85.54 119.51,87.17 119.11,87.58 114.52,87.58 114.13,87.96 114.13,92.07 114.52,92.45 117.91,92.45 118.32,92.86 118.32,94.05 118.66,94.38 119.99,94.38 120.35,94.02 120.35,93.09 119.75,92.49 119.75,91.47 119.61,91.33 119.1,91.33 118.87,91.56 J9.5
USB30_RXP: length 26.2
  BOTTOM w0.132: R84.1 119.14,83.57 U10.10 U10.1 119.14,85.41 119.27,85.54 119.27,87.08 119.01,87.34 114.42,87.34 113.89,87.87 113.89,92.17 114.42,92.69 117.82,92.69 118.08,92.96 118.08,94.15 118.56,94.62 120.09,94.62 120.59,94.12 120.59,92.99 119.99,92.39 119.99,92.06 120.17,91.88 J9.6
USB30_TXN: length 10.4
  BOTTOM w0.132: C75.1 126.23,83.06 U11.7 U11.4 126.23,85.41 126.36,85.54 126.36,87.51 125.78,88.09 125.78,89.08 125.22,89.64 125.22,90.47 125.75,91 125.75,91.72 125.5,91.97 124.96,91.97 J9.8
USB30_TXP: length 10.5
  BOTTOM w0.132: J9.9 126.25,91.88 125.99,91.62 125.99,90.9 125.46,90.37 125.46,89.73 126.02,89.18 126.02,88.19 126.6,87.61 126.6,85.54 126.73,85.41 U11.5 U11.6 126.73,83.57 C76.1
USB_HUB_3V3: length 32.3
  TOP w0.305: v1(134.98,79.5) R101.2 R105.2 ; v1(143.76,76.07) 143.37,76.46 C96.1 144.63,77.21 145.03,77.62 145.03,78.94 144.58,79.39 U14.1 ; U14.20 140.35,77.24 C95.1 140.33,76.32 v1(140.08,76.07) 136.02,76.07 135.64,76.44 R104.2
  ART04 w0.305: v1(143.76,76.07) v1(140.08,76.07) 138.35,76.07 138.05,76.38 138.05,79.11 137.66,79.5 v1(134.98,79.5)
  BOTTOM w0.305: v1(140.08,76.07) 140.08,76.83 139.71,77.21 C94.1 R100.2
USB_HUB_DM1: length 6.9
  TOP w0.132: U14.11 140.35,83.4 140.22,83.53 140.22,83.83 140.46,84.07 140.46,84.58 140.46,84.61 140.6,84.74 U12.2 U12.9 140.6,86.17 140.47,86.3 140.47,86.68 141.22,87.43 141.22,88.01 141.71,88.5 J10.2
USB_HUB_DM2: length 12.6
  TOP w0.132: U14.9 141.35,83.14 141.22,83.27 141.22,83.56 141.97,84.31 141.97,84.64 142.1,84.77 U12.5 U12.6 142.1,86.17 141.97,86.3 141.97,86.68 142.23,86.94 143.05,86.94 143.46,87.35 143.46,89.59 142.98,90.07 141.35,90.07 141.22,90.2 141.22,90.62 J10.8
USB_HUB_DM3: length 61.8
  TOP w0.132: R269.2 126.99,58.93 126.99,56.91 127.78,56.12 136.42,56.12 137.1,56.8 137.1,73.72 137.88,74.5 142.88,74.5 143.59,75.21 145.05,75.21 arc(145.13,75.24) 145.16,75.32 arc(145.19,75.4) 145.28,75.44 145.58,75.44 arc(145.66,75.4) 145.69,75.32 arc(145.72,75.24) 145.8,75.21 146.1,75.21 arc(146.18,75.24) 146.22,75.32 arc(146.25,75.4) 146.33,75.44 146.63,75.44 arc(146.71,75.4) 146.75,75.32 arc(146.78,75.24) 146.86,75.21 147.16,75.21 arc(147.24,75.24) 147.27,75.32 arc(147.31,75.4) 147.39,75.44 147.69,75.44 arc(147.77,75.4) 147.8,75.32 arc(147.84,75.24) 147.92,75.21 148.62,75.21 149.25,75.84 149.25,76.93 149.1,77.08 149.1,77.46 149.25,77.61 149.25,77.88 150.04,78.67 150.04,83.55 149.72,83.87 148.35,83.87 148.2,83.72 147.82,83.72 147.67,83.87 147.29,83.87 147.14,83.72 146.77,83.72 146.61,83.87 146.24,83.87 146.08,83.72 145.71,83.72 145.56,83.87 145.18,83.87 145.03,83.72 144.65,83.72 144.5,83.87 144.12,83.87 143.97,83.72 143.6,83.72 143.44,83.87 142.53,83.87 142.22,83.56 142.22,83.31 142.35,83.18 U14.7
USB_HUB_DM4: length 11.6
  TOP w0.132: v1(144.82,81.25) 144.55,81.52 143.98,81.52 143.85,81.39 U14.5
  BOTTOM w0.132: v1(144.82,81.25) 144.82,81.43 145.07,81.67 145.43,81.67 145.83,81.26 145.83,80.98 145.69,80.84 145.69,80.46 145.83,80.32 145.83,79.44 145.55,79.16 141.85,79.16 141.36,78.66 141.36,77.6 R143.1
USB_HUB_DP1: length 6.9
  TOP w0.132: U14.12 139.85,83.4 139.98,83.53 139.98,83.93 140.22,84.17 140.22,84.48 140.22,84.62 140.1,84.74 U12.1 U12.10 140.1,86.17 140.23,86.3 140.23,86.78 140.98,87.53 140.98,88.05 140.53,88.5 J10.3
USB_HUB_DP2: length 12.6
  TOP w0.132: U14.10 140.85,83.14 140.98,83.27 140.98,83.66 141.73,84.41 141.73,84.64 141.6,84.77 U12.4 U12.7 141.6,86.17 141.73,86.3 141.73,86.78 142.13,87.18 142.95,87.18 143.22,87.45 143.22,89.49 142.88,89.83 141.25,89.83 140.98,90.1 140.98,90.62 J10.9
USB_HUB_DP3: length 61.8
  TOP w0.132: R270.2 126.75,58.93 126.75,56.81 127.68,55.88 136.52,55.88 137.34,56.7 137.34,73.62 137.98,74.26 142.97,74.26 143.69,74.97 148.71,74.97 149.49,75.74 149.49,77.78 150.28,78.57 150.28,83.65 149.82,84.11 142.43,84.11 141.98,83.66 141.98,83.3 141.85,83.17 U14.8
USB_HUB_DP4: length 11.7
  TOP w0.132: v1(144.82,82.04) 144.55,81.76 143.98,81.76 143.85,81.89 U14.6
  BOTTOM w0.132: R142.1 141.6,77.6 141.6,78.56 141.95,78.92 145.65,78.92 146.07,79.34 146.07,81.36 145.53,81.91 144.95,81.91 v1(144.82,82.04)
N16593695: length 0.6
  BOTTOM w0.381: R10.1 v1(23.36,32.15)
N16593775: length 2.1
  BOTTOM w0.381: R10.2 22.35,32.77 C20.1 21.33,32.78 R13.2
N16593791: length 4.2
  TOP w0.203: U2.11 v1(17.28,31)
  BOTTOM w0.152: 18.3,31.77 R17.1
  BOTTOM w0.305: v1(17.28,31) 17.52,31 R17.1 ; 18.3,31.77 R12.2 R13.1
N16594273: length 10.2
  BOTTOM w0.508: J5.5 18.2,100.88 L1.1 14.34,101.4 10.26,101.4 9.79,100.92 J5.1
N16594503: length 3.9
  TOP w0.152: U2.12 16.78,30.5 v1(16.28,31)
  BOTTOM w0.152: v1(16.28,31) R9.2 R16.1 C26.1
N16594633: length 2.2
  TOP w0.152: U2.3 16.78,26.79 16.6,26.62 v1(16.19,26.62)
  BOTTOM w0.152: R15.2 16.19,26.88 v1(16.19,26.62)
N16594645: length 2.7
  TOP w0.152: U2.6 18.28,26.84 18.45,26.67 v1(18.67,26.67)
  BOTTOM w0.152: v1(18.67,26.67) 18.79,26.79 R18.1 R14.2
N16594663: length 4.6
  TOP w0.152: U2.9 v1(18.28,31)
  BOTTOM w0.152: v1(18.28,31) 17.79,30.52 C25.1 R14.1 16.77,28.46 R15.1
N16605614: length 16.1
  BOTTOM w1.016: J6.16 69.46,91.05 R42.1 70.23,91.82 C36.1 73.16,91.05 J6.15
N16605678: length 5.3
  BOTTOM w0.381: R39.1 67.56,95.38 67.03,95.91 J6.13
N16605786: length 5.1
  TOP w0.152: U4.32 73.63,76.47 73.93,76.17 73.93,75.43 74.72,74.64 v1(74.72,74.51)
  BOTTOM w0.152: v1(74.72,74.51) 74.3,74.94 74.3,75.45 73.66,76.09 R45.1
N16605856: length 5.3
  BOTTOM w0.381: C35.1 75.45,83.82 J6.1
N16606070: length 4.8
  BOTTOM w0.381: J6.12 75.21,95.78 74.8,95.38 R40.1
N16606548: length 3
  TOP w0.152: v1(74.47,80.11) 74.47,80.1 73.64,79.27 U4.39
  BOTTOM w0.152: R25.1 74.22,80.11 v1(74.47,80.11)
N16607242: length 3.2
  TOP w0.173: U4.25 70.26,73.87 R23.2
N16607246: length 3.7
  TOP w0.173: U4.24 69.86,74.09 68.99,73.22 68.59,73.22 R24.2
N16607250: length 4.3
  TOP w0.173: R26.2 67.98,73.62 68.86,73.62 69.46,74.22 U4.23
N16607260: length 4.8
  TOP w0.173: U4.22 69.06,74.36 68.73,74.03 67.38,74.03 R27.2
N16607264: length 2.7
  TOP w0.173: U4.27 R28.2
N16607268: length 3
  TOP w0.173: R29.2 70.66,73.25 U4.26
N16607434: length 2.5
  TOP w0.152: Y1.1 77.36,80.91 C33.1 R384.1
N16607930: length 2.6
  TOP w0.152: v1(73.58,74.51) 73.58,75.76 73.27,76.07 U4.31
  BOTTOM w0.152: v1(73.58,74.51) 73.65,74.59 R35.2
N16608272: length 7.8
  TOP w0.152: Y1.3 79.24,78.96 78.93,79.26 76.84,79.26 C34.1 76.44,78.87 R385.2 75.25,78.07 U4.36
N16611232: length 11.3
  TOP w0.152: v1(48.62,79.42) 48.77,79.27 U3.12
  BOTTOM w0.152: C58.1 48.72,79.52 v1(48.62,79.42) 48.52,79.51 48.52,81.49 48.08,81.93 45.01,81.93 44.7,81.63 R70.2 43.56,80.52 R69.2 43.55,79.73 D7.2
N16611438: length 16
  BOTTOM w1.016: J7.16 51.05,91.05 R71.1 51.69,91.69 C57.1 54.36,91.05 J7.15
N16611542: length 5.8
  TOP w0.152: U3.32 55.32,76.47 55.53,76.25 55.53,75.7 55.91,75.33 55.91,74.56 v1(56.26,74.21)
  BOTTOM w0.152: R74.1 55.89,75.56 55.89,74.58 v1(56.26,74.21)
N16611608: length 3.4
  BOTTOM w0.305: J7.1 58.45,85.22 C56.1
N16612282: length 3
  TOP w0.152: v1(56.07,80.11) 56.07,80.1 55.24,79.27 U3.39
  BOTTOM w0.152: v1(56.07,80.11) 55.47,79.52 R53.1
N16612988: length 3.3
  TOP w0.173: R51.2 51.86,74.12 U3.25
N16612992: length 3.9
  TOP w0.173: U3.24 51.46,74.25 50.38,73.17 49.9,73.17 R52.2
N16612996: length 4.4
  TOP w0.173: R54.2 49.26,73.55 50.22,73.55 51.06,74.38 U3.23
N16613006: length 5
  TOP w0.173: U3.22 50.66,74.52 50.07,73.93 48.62,73.93 R55.2
N16613010: length 2.8
  TOP w0.173: R56.2 52.66,72.89 U3.27
N16613014: length 3.1
  TOP w0.173: U3.26 52.26,73.5 R57.2
N16613204: length 2.5
  TOP w0.152: R387.1 C54.1 59.58,80.91 Y2.1
N16613212: length 8.4
  TOP w0.152: Y2.3 61.46,78.96 61.15,79.26 59.06,79.26 C55.1 57.67,77.87 R386.2 57.47,78.07 U3.36
N16613364: length 29.1
  TOP w0.254: J7.11 59.35,97.33 58.93,96.92 56.9,96.92 56.13,96.15 56.13,90.18 56.9,89.42 58.42,89.42 59.18,88.66 61.34,88.66 61.85,88.15 61.85,83.6 v1(62.19,83.26)
  BOTTOM w0.203: R64.1 59.82,80.32 60.22,80.72 60.22,82.31 60.55,82.64 61.58,82.64 v1(62.19,83.26)
N16613452: length 3.3
  BOTTOM w0.381: R66.1 48.7,98.93 J7.13
N16613812: length 2.9
  TOP w0.152: v1(55.38,74.54) 55.35,74.58 55.35,75.36 55.18,75.52 55.18,75.91 55.02,76.07 U3.31
  BOTTOM w0.152: R63.2 55.24,74.69 v1(55.38,74.54)
N16620498: length 1.5
  BOTTOM w0.152: R95.1 17.13,88.74 U6.3
N16620622: length 3.5
  BOTTOM w0.152: U6.4 17.13,83.21 C86.1 R93.2
N16621700: length 20.9
  TOP w0.508: J8.3 22.53,102.12 29.53,102.12 J8.2
  ART03 w0.508: J8.4 J8.3 ; J8.1 J8.2
  BOTTOM w0.508: L12.1 30.52,101.47 J8.2
N16621974: length 3.4
  TOP w0.132: R106.1 137.03,82.18 137.22,82.18 137.35,82.04 137.35,81.36 137.69,81.02 138.21,81.02 138.34,80.89 U14.15
N16621978: length 3.4
  TOP w0.132: R107.1 137.03,82.41 137.32,82.41 137.59,82.14 137.59,81.46 137.79,81.26 138.21,81.26 138.34,81.39 U14.14
N16622106: length 29.8
  TOP w0.762: J10.11 J10.12
  BOTTOM w0.762: J10.5 J10.11 134.62,94.37 L13.1 ; J10.6 J10.12
N16622154: length 4.4
  TOP w0.152: R111.1 C105.1 C104.1 162.94,98.42 U15.2
N16622302: length 3.2
  TOP w0.152: U15.3 161.67,98.42 R109.2 R110.2
N16622762: length 30.9
  TOP w0.762: J9.22 128.79,94.73 116.95,94.73 J9.19
  ART03 w0.508: J9.20 J9.19 ; J9.21 J9.22
  BOTTOM w0.762: L11.1 114.47,97.22 J9.19
N16624042: length 3.9
  BOTTOM w0.152: R103.1 138.68,97.89 139.02,97.54 139.8,97.54 140.15,97.89 U13.3
N16624166: length 3.8
  BOTTOM w0.152: R102.2 C99.1 139.83,100.2 140.15,100.52 U13.4
N16624284: length 2.2
  BOTTOM w0.152: U7.3 120.21,99.75 120.02,99.95 119.24,99.95 R99.1
N16624408: length 4.9
  BOTTOM w0.152: R96.2 117.51,101.25 118.45,101.25 C89.1 119.37,100.33 120.04,100.33 120.21,100.5 U7.4
N16625162: length 6.5
  TOP w0.152: U14.3 145.4,80.39 C102.1 145.98,80.44 148.31,80.44 148.58,80.17 Y3.1
N16625190: length 4.3
  TOP w0.152: Y3.3 146.18,81.67 C103.1 145.32,80.81 144.64,80.81 144.56,80.89 U14.4
N16625358: length 4
  TOP w0.152: U14.13 138.25,81.89 138.05,82.09 138.05,83.56 137.79,83.82 R108.1
N16625468: length 3.7
  TOP w0.152: U14.17 137.04,79.89 R101.1
  TOP w0.173: R101.1 C98.1
N16625496: length 2.5
  TOP w0.152: U14.16 136.89,80.39 R105.1
N16625548: length 3.9
  TOP w0.152: U14.18 137.68,79.39 137.34,79.05 137.34,77.91 R104.1
N16630017: length 3.6
  TOP w0.152: R121.2 19.06,79.9 19.3,79.9 20,79.21 U16.26
N16630071: length 2.7
  TOP w0.152: v1(24.1,74.81) 23.65,75.26 U16.17
  BOTTOM w0.305: v1(24.1,74.81) 24.27,74.65 C106.1
N16630361: length 3.4
  TOP w0.152: C112.1 20.9,79.06 U16.24
N16630365: length 3.2
  TOP w0.152: C113.1 21.35,79.63 U16.23
N16630441: length 3
  TOP w0.152: C115.1 21.8,80.19 U16.22
N16630445: length 3.5
  TOP w0.152: C117.1 22.45,80.49 U16.21
N16630545: length 4.2
  TOP w0.152: U16.20 23.65,76.61 v1(24.1,76.16)
  BOTTOM w0.152: v1(24.1,76.16) 23.56,76.7 22.75,76.7 C118.1
N16630549: length 1.6
  TOP w0.152: U16.19 v1(23.1,76.16)
  BOTTOM w0.152: v1(23.1,76.16) 23.05,76.21 C119.1
N16630553: length 3.5
  TOP w0.152: U16.10 20,72.97 19.81,72.79 19.18,72.79 v1(18.65,72.26)
  BOTTOM w0.152: v1(18.65,72.26) 19.43,73.03 C120.1
N16778766: length 25.4
  BOTTOM w0.152: Q12.1 Q11.1 105.91,73.09 106.27,72.72 106.27,70.94 Q13.1 ; Q13.1 104.99,69.63 106.25,68.38 106.25,66.67 105.87,66.29 R171.1 R169.2 ; Q13.1 99.8,69.66 Q10.1
N16778768: length 8.1
  BOTTOM w0.152: Q12.3 98.7,72.13 R166.2 R165.2
N16778770: length 17.5
  BOTTOM w0.152: R167.2 R168.2 91.57,76.14 91.92,75.78 94.16,75.78 95.5,74.44 95.5,72.4 95.76,72.15 96.77,72.15 100.22,68.71 Q13.3
N16778784: length 42.3
  ART03 w0.508: J16.G3 J16.G4
  ART04 w0.508: J16.G1 J16.G2
  PWR05 w0.508: J16.G3 89.04,85.2 89.75,84.48 89.75,82.25 89,81.5 89,80.53 87.99,79.52 83.55,79.52 82.54,80.53 J16.G1
  BOTTOM w0.173: 82.54,100.2 R156.1
  BOTTOM w0.508: J16.G2 82.54,100.2
N16779726: length 7.8
  BOTTOM w0.152: R158.2 94.29,69.93 Q8.1 90.84,69.93 90.54,69.62 90.54,69.27 90.25,68.98 Q9.3
N16779736: length 11.5
  BOTTOM w0.152: R159.1 85.42,76.55 85.42,71.95 85.78,71.58 85.78,70.18 R160.1 86.69,69.93 Q9.1
N16779830: length 10.4
  BOTTOM w0.152: Q10.3 94.32,74.86 93.93,75.25 89.69,75.25 89.28,75.66 R162.2 R161.2
N16779838: length 10.9
  BOTTOM w0.152: R163.2 R164.2 96.01,75.45 98.11,73.35 99.36,73.35 100.58,72.13 Q11.3
N16779929: length 2.4
  BOTTOM w0.152: R153.2 90.94,72.66 C142.1 90.2,72.65 Q7.1
N16781420: length 13.9
  BOTTOM w0.152: Q20.1 Q21.1 Q22.1 Q19.1 123.25,77.66 R192.1
  BOTTOM w0.173: R192.1 R190.2
N16781422: length 10.8
  BOTTOM w0.152: R186.2 105.01,76.99 R187.2 106.55,75.45 107.24,75.45 107.67,75.02 112.19,75.02 112.48,75.31 Q21.3
N16781424: length 17.7
  BOTTOM w0.152: Q22.3 116.04,75.06 115.6,74.61 107.24,74.61 106.82,75.03 105.46,75.03 104.85,75.64 103.06,75.64 102.74,75.96 R189.2 R188.2
N16781438: length 43.9
  ART03 w0.508: J17.G3 J17.G4 ; J17.G1 J17.G2
  PWR05 w0.508: J17.G3 99.84,84.38 100.1,84.11 100.1,79.67 99.16,78.73 94.03,78.73 93.34,79.42 J17.G1
  BOTTOM w0.173: 93.34,92.62 J17.G2
  BOTTOM w0.508: R177.1 93.34,92.62
N16782370: length 7.4
  BOTTOM w0.152: R179.2 115.18,65.15 Q18.3 117.04,65.15 117.35,65.45 117.35,68.81 Q17.1
N16782390: length 40.9
  ART04 w0.152: v1(119.84,65.65) 117.3,65.65 116.97,65.98 116.97,71.87 116.66,72.18 110.13,72.18 109.83,71.87 109.83,69.74 109.52,69.43 104.24,69.43 103.94,69.74 103.94,75.78 103.63,76.09 v1(96.9,76.09)
  BOTTOM w0.152: v1(96.9,76.09) 97.13,76.09 97.28,76.24 R180.1 ; Q18.1 118.8,66.1 R181.1 v1(119.84,65.65)
N16782474: length 23.8
  BOTTOM w0.152: Q19.3 117.73,76.71 117.14,76.12 117.14,74.59 116.79,74.23 107.04,74.23 106.61,74.65 105.18,74.65 104.6,75.23 101.3,75.23 100.58,75.94 R183.2 R182.2
N16782482: length 2.6
  BOTTOM w0.152: R184.2 R185.2 107.59,76.71 Q20.3
N16782583: length 2.4
  BOTTOM w0.152: R174.2 120.25,72.63 C154.1 118.52,72.63 Q16.1
N16783799: length 36.2
  ART03 w0.508: J18.G1 J18.G2 ; J18.G3 J18.G4
  BOTTOM w0.508: J18.G2 104.14,99.12 104.72,99.7 R195.1 110.64,99.68 J18.G4
N16783872: length 1
  TOP w0.173: R200.1 R197.1
N16786078: length 1.7
  TOP w0.381: R209.1 129.88,76.97 D46.1
N16791174: length 3.2
  BOTTOM w0.152: Q28.1 131.68,82.05 R211.1
  BOTTOM w0.173: R212.2 R211.1
N16794123: length 3.9
  TOP w0.152: Q27.1 133.79,83.49 R213.2 v1(133.34,84.71)
  BOTTOM w0.152: R215.1 v1(133.34,84.71)
N16794280: length 2.6
  TOP w0.152: Q27.3 133.77,80.22 133.98,80.02 v1(133.98,79.5)
  BOTTOM w0.152: v1(133.98,79.5) 133.85,79.5 R214.1
N16795019: length 7.4
  TOP w0.152: C316.1 120.46,83.51 Q29.1 120.21,82.01 120.21,80.78 120.52,80.47 R193.2 R194.1
N16796110: length 3.4
  BOTTOM w0.152: R215.2 132.84,82.94 Q28.3
N16803409: length 6.9
  TOP w0.173: U25.4 v1(154.57,68.41)
  BOTTOM w0.152: C157.1 R218.1 R227.1 154.76,70.37 155.04,70.09 155.04,68.88 v1(154.57,68.41)
N16803499: length 3.4
  TOP w0.173: U25.5 v1(154.57,69.36)
  BOTTOM w0.152: v1(154.57,69.36) R221.1 R222.1
N16803635: length 8
  TOP w0.152: Y4.1 121.02,46.25 120.14,47.13 118.75,47.13 118.36,46.75 117.25,46.75 C164.1 116.27,46.43 U26.5
N16803642: length 2.5
  TOP w0.152: U26.10 116.57,49.68 R234.1
N16803673: length 4.1
  TOP w0.152: U26.15 v1(109.42,47.08)
  BOTTOM w0.152: v1(109.42,47.08) 109.36,47.01 R235.2 C167.1 C166.1
N16803735: length 5.3
  TOP w0.114: R216.1 103.59,44.03 107.02,44.03 107.22,43.83 U26.20
N16803772: length 5.2
  TOP w0.114: U26.19 107.22,44.48 107.02,44.27 103.42,44.27 R217.1
N16803867: length 5.5
  TOP w0.114: R228.1 103.57,45.59 103.95,45.98 105.48,45.98 106.13,45.33 107.02,45.33 107.22,45.13 U26.18
N16803869: length 5.5
  TOP w0.114: R229.1 103.57,46.61 103.95,46.22 105.58,46.22 106.23,45.57 107.02,45.57 107.22,45.78 U26.17
N16803965: length 2.9
  TOP w0.152: R230.1 C165.1 119.51,48.39 Y4.3
N16804075: length 2.6
  TOP w0.152: U26.6 116.3,47.08 R230.2
N16804652: length 3.1
  TOP w0.152: R237.1 161.04,83.32 J19.38
N16804754: length 3.1
  TOP w0.173: J19.10 154.05,86.45 R236.1
N16810459: length 5.2
  TOP w0.114: R238.1 103.42,47.93 107.02,47.93 107.22,47.73 U26.14
